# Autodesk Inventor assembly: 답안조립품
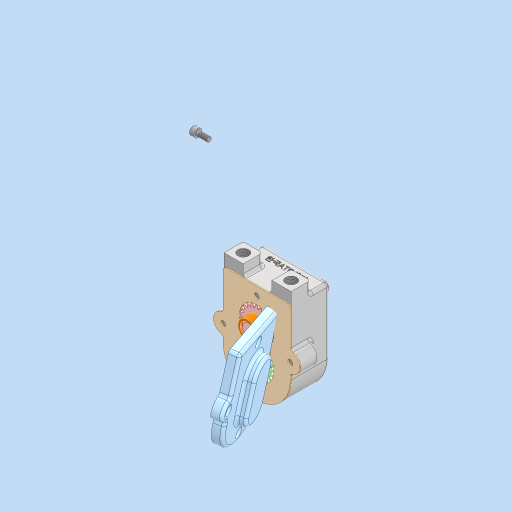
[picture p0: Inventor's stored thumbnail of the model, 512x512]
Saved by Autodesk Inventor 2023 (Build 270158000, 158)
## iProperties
Created: 2024-03
Part Number: 답안조립품
Document SubType Name: Assembly
Designer: asung
Author: asung
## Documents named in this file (8)
- C:\Users\asung\Desktop\740304V1001\답안조립품.iam
- C:\Users\asung\Desktop\740304V1001\본체.ipt
- C:\Users\asung\Desktop\740304V1001\오일레스 부시.ipt
- C:\Users\asung\Desktop\740304V1001\스퍼기어.ipt
- C:\Users\asung\Desktop\740304V1001\구동기어.ipt
- C:\Users\asung\Desktop\740304V1001\가스켓.ipt
- C:\Users\asung\Desktop\740304V1001\육각 소켓 머리 볼트 M5x12.ipt
- C:\Users\asung\Desktop\740304V1001\커버.ipt
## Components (2 placed, 2 different names)
1. 구동기어:1
2. 가스켓:1
